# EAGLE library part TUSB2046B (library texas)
4-PORT HUB FOR THE UNIVERSAL SERIAL BUS WITH OPTIONAL SERIAL EEPROM INTERFACE Auto generated by make-symbol-device-package-bsdl.ulp Rev. 30 Source: http://focus.ti.com/lit/ds/symlink/tusb2046b.pdf
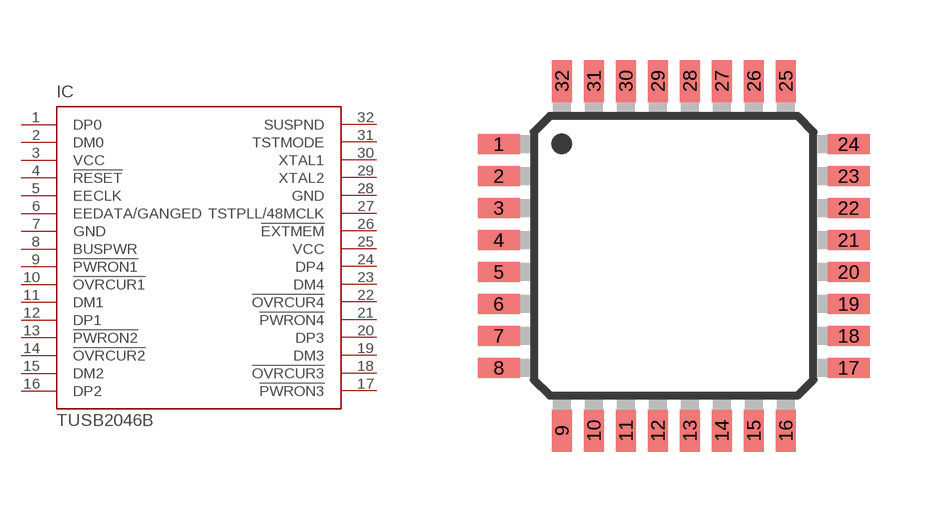
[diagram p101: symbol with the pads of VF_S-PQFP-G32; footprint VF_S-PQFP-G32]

Designator prefix IC

## TUSB2046BVFR (MF: TEXAS INSTRUMENTS; MPN: TUSB2046BVFR; OC_FARNELL: 1470507; OC_NEWARK: 77C1806)  [VF_S-PQFP-G32]
1  DP0
2  DM0
3  VCC  pwr
4  !RESET  in
5  EECLK  out
6  EEDATA/GANGED
7  GND  pwr
8  BUSPWR  in
9  !PWRON1  out
10  !OVRCUR1  in
11  DM1
12  DP1
13  !PWRON2  out
14  !OVRCUR2  in
15  DM2
16  DP2
17  !PWRON3  out
18  !OVRCUR3  in
19  DM3
20  DP3
21  !PWRON4  out
22  !OVRCUR4  in
23  DM4
24  DP4
25  VCC  pwr
26  !EXTMEM  in
27  TSTPLL/48MCLK
28  GND  pwr
29  XTAL2  out
30  XTAL1  in
31  TSTMODE  in
32  SUSPND  out

## Footprint VF_S-PQFP-G32 (pad centres in mm)
VF (S-PQFP-G32) Auto generated by make-symbol-device-package-bsdl.ulp Rev. 30 Souirce: http://focus.ti.com/lit/ds/symlink/tusb2046b.pdf
smd 1.05 x 0.5: 1 -4.375,2.8; 2 -4.375,2; 3 -4.375,1.2; 4 -4.375,0.4; 5 -4.375,-0.4; 6 -4.375,-1.2; 7 -4.375,-2; 8 -4.375,-2.8; 17 4.375,-2.8; 18 4.375,-2; 19 4.375,-1.2; 20 4.375,-0.4; 21 4.375,0.4; 22 4.375,1.2; 23 4.375,2; 24 4.375,2.8
smd 0.5 x 1.05: 9 -2.8,-4.375; 10 -2,-4.375; 11 -1.2,-4.375; 12 -0.4,-4.375; 13 0.4,-4.375; 14 1.2,-4.375; 15 2,-4.375; 16 2.8,-4.375; 25 2.8,4.375; 26 2,4.375; 27 1.2,4.375; 28 0.4,4.375; 29 -0.4,4.375; 30 -1.2,4.375; 31 -2,4.375; 32 -2.8,4.375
